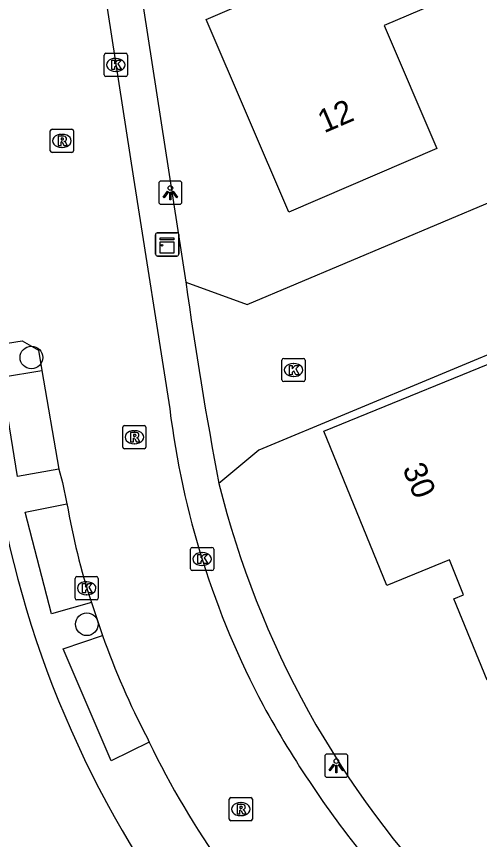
# Model space of a CAD drawing. Extents: x 158474 to 159560, y 388525 to 389605.
# Drawn here: x 158564.62 to 158584.59, y 389003.68 to 389039.16 of the extents above; entities that cross this region are included whole.
import ezdxf

# ---------------------------------------------------------------- set-up
doc = ezdxf.new("R2010")
doc.units = 0
for name, color, linetype in [('IMGEO_Boom', 7, 'Continuous'), ('IMGEO_Kast', 7, 'Continuous'), ('IMGEO_Kolk', 7, 'Continuous'), ('IMGEO_Lichtpunt', 7, 'Continuous'), ('IMGEO_Pand', 7, 'Continuous'), ('IMGEO_Pand_nummerreeks', 7, 'Continuous'), ('IMGEO_Rijbaan_lokaal_open', 7, 'Continuous'), ('IMGEO_Rioolput', 7, 'Continuous'), ('IMGEO_Voetpad_open', 7, 'Continuous')]:
    doc.layers.add(name, color=color, linetype=linetype)

msp = doc.modelspace()

# ---------------------------------------------------------------- linework, layer by layer
at = {"layer": 'IMGEO_Boom'}
for centre in [(158565.26, 389024.458), (158567.65, 389012.957)]:
    msp.add_circle(centre, 0.489, dxfattribs=at)
at = {"layer": 'IMGEO_Kast'}
for p, q in [((158570.614, 389028.908), (158570.614, 389029.749)), ((158570.614, 389029.749), (158570.614, 389028.908)), ((158570.689, 389029.833), (158571.53, 389029.833)), ((158571.53, 389029.833), (158570.689, 389029.833)), ((158571.614, 389029.758), (158571.614, 389028.917)), ((158571.614, 389028.917), (158571.614, 389029.758)), ((158571.539, 389028.833), (158570.698, 389028.833)), ((158570.698, 389028.833), (158571.539, 389028.833))]:
    msp.add_line(p, q, dxfattribs=at)
for points in [[(158570.809, 389029.623), (158571.409, 389029.623), (158571.409, 389029.538), (158570.809, 389029.538), (158570.809, 389029.623)], [(158570.809, 389029.448), (158571.409, 389029.448), (158571.409, 389028.959), (158570.809, 389028.959), (158570.809, 389029.448)]]:
    msp.add_lwpolyline(points, dxfattribs=at)
msp.add_circle((158570.893, 389029.297), 0.0377, dxfattribs=at)
for centre, start, end in [((158570.692, 389029.755), 92.4484, 184.2845), ((158570.692, 389029.755), 92.4484, 184.2845), ((158571.536, 389029.755), 2.4484, 94.2845), ((158571.536, 389029.755), 2.4484, 94.2845), ((158570.692, 389028.911), 182.4484, 274.2845), ((158570.692, 389028.911), 182.4484, 274.2845), ((158571.536, 389028.911), 272.4484, 4.2845), ((158571.536, 389028.911), 272.4484, 4.2845)]:
    msp.add_arc(centre, 0.0779, start, end, dxfattribs=at)
at = {"layer": 'IMGEO_Kolk'}
for p, q in [((158568.401, 389036.646), (158568.401, 389037.498)), ((158568.476, 389037.572), (158569.328, 389037.572)), ((158568.889, 389037.352), (158568.914, 389037.352)), ((158569.402, 389037.498), (158569.402, 389036.646)), ((158568.912, 389036.792), (158568.887, 389036.792)), ((158569.328, 389036.572), (158568.476, 389036.572)), ((158576.066, 389023.492), (158576.066, 389024.344)), ((158576.141, 389024.418), (158576.993, 389024.418)), ((158576.554, 389024.198), (158576.579, 389024.198)), ((158577.067, 389024.344), (158577.067, 389023.492)), ((158576.577, 389023.638), (158576.552, 389023.638)), ((158576.993, 389023.418), (158576.141, 389023.418)), ((158572.121, 389015.345), (158572.121, 389016.197)), ((158572.196, 389016.271), (158573.048, 389016.271)), ((158572.609, 389016.051), (158572.634, 389016.051)), ((158573.122, 389016.197), (158573.122, 389015.345)), ((158572.632, 389015.491), (158572.607, 389015.491)), ((158567.218, 389015.009), (158568.07, 389015.009)), ((158573.048, 389015.271), (158572.196, 389015.271)), ((158567.143, 389014.083), (158567.143, 389014.935)), ((158567.631, 389014.789), (158567.656, 389014.789)), ((158568.144, 389014.935), (158568.144, 389014.083)), ((158568.07, 389014.009), (158567.218, 389014.009)), ((158567.654, 389014.229), (158567.629, 389014.229))]:
    msp.add_line(p, q, dxfattribs=at)
for points in [[(158568.401, 389036.646), (158568.401, 389037.498)], [(158568.476, 389037.572), (158569.328, 389037.572)], [(158569.402, 389037.498), (158569.402, 389036.646)], [(158568.722, 389037.272), (158568.845, 389037.272), (158568.845, 389037.121), (158568.975, 389037.272), (158569.139, 389037.272), (158568.993, 389037.121), (158569.146, 389036.872), (158568.994, 389036.872), (158568.909, 389037.036), (158568.845, 389036.969), (158568.845, 389036.872), (158568.722, 389036.872), (158568.722, 389037.272)], [(158569.328, 389036.572), (158568.476, 389036.572)], [(158576.066, 389023.492), (158576.066, 389024.344)], [(158576.141, 389024.418), (158576.993, 389024.418)], [(158577.067, 389024.344), (158577.067, 389023.492)], [(158576.387, 389024.118), (158576.51, 389024.118), (158576.51, 389023.967), (158576.64, 389024.118), (158576.804, 389024.118), (158576.658, 389023.967), (158576.811, 389023.718), (158576.659, 389023.718), (158576.574, 389023.882), (158576.51, 389023.815), (158576.51, 389023.718), (158576.387, 389023.718), (158576.387, 389024.118)], [(158576.993, 389023.418), (158576.141, 389023.418)], [(158572.121, 389015.345), (158572.121, 389016.197)], [(158572.196, 389016.271), (158573.048, 389016.271)], [(158573.122, 389016.197), (158573.122, 389015.345)], [(158572.442, 389015.971), (158572.565, 389015.971), (158572.565, 389015.82), (158572.695, 389015.971), (158572.859, 389015.971), (158572.713, 389015.82), (158572.866, 389015.571), (158572.714, 389015.571), (158572.629, 389015.735), (158572.565, 389015.668), (158572.565, 389015.571), (158572.442, 389015.571), (158572.442, 389015.971)], [(158567.218, 389015.009), (158568.07, 389015.009)], [(158573.048, 389015.271), (158572.196, 389015.271)], [(158567.143, 389014.083), (158567.143, 389014.935)], [(158567.464, 389014.709), (158567.587, 389014.709), (158567.587, 389014.558), (158567.717, 389014.709), (158567.881, 389014.709), (158567.735, 389014.558), (158567.888, 389014.309), (158567.736, 389014.309), (158567.651, 389014.473), (158567.587, 389014.406), (158567.587, 389014.309), (158567.464, 389014.309), (158567.464, 389014.709)], [(158568.144, 389014.935), (158568.144, 389014.083)], [(158568.07, 389014.009), (158567.218, 389014.009)]]:
    msp.add_lwpolyline(points, dxfattribs=at)
for centre, start, end in [((158568.478, 389037.496), 91.552, 178.448), ((158568.478, 389037.496), 91.552, 178.448), ((158569.326, 389037.496), 1.552, 88.448), ((158569.326, 389037.496), 1.552, 88.448), ((158568.478, 389036.648), 181.552, 268.448), ((158568.478, 389036.648), 181.552, 268.448), ((158569.326, 389036.648), 271.552, 358.448), ((158569.326, 389036.648), 271.552, 358.448), ((158576.143, 389024.342), 91.552, 178.448), ((158576.143, 389024.342), 91.552, 178.448), ((158576.991, 389024.342), 1.552, 88.448), ((158576.991, 389024.342), 1.552, 88.448), ((158576.143, 389023.494), 181.552, 268.448), ((158576.143, 389023.494), 181.552, 268.448), ((158576.991, 389023.494), 271.552, 358.448), ((158576.991, 389023.494), 271.552, 358.448), ((158572.198, 389016.195), 91.552, 178.448), ((158572.198, 389016.195), 91.552, 178.448), ((158573.046, 389016.195), 1.552, 88.448), ((158573.046, 389016.195), 1.552, 88.448), ((158572.198, 389015.347), 181.552, 268.448), ((158572.198, 389015.347), 181.552, 268.448), ((158573.046, 389015.347), 271.552, 358.448), ((158573.046, 389015.347), 271.552, 358.448), ((158567.22, 389014.933), 91.552, 178.448), ((158567.22, 389014.933), 91.552, 178.448), ((158568.068, 389014.933), 1.552, 88.448), ((158568.068, 389014.933), 1.552, 88.448), ((158567.22, 389014.085), 181.552, 268.448), ((158567.22, 389014.085), 181.552, 268.448), ((158568.068, 389014.085), 271.552, 358.448), ((158568.068, 389014.085), 271.552, 358.448)]:
    msp.add_arc(centre, 0.0765, start, end, dxfattribs=at)
for centre, major_axis, ratio, start_param, end_param in [((158568.888, 389037.072), (-0.387, 0.002), 0.722429, 4.712389, 7.853982), ((158568.913, 389037.072), (-0.39, 0.002), 0.717154, 1.570796, 4.712389), ((158576.553, 389023.918), (-0.387, 0.002), 0.722429, 4.712389, 7.853982), ((158576.578, 389023.918), (-0.39, 0.002), 0.717154, 1.570796, 4.712389), ((158572.608, 389015.771), (-0.387, 0.002), 0.722429, 4.712389, 7.853982), ((158572.633, 389015.771), (-0.39, 0.002), 0.717154, 1.570796, 4.712389), ((158567.63, 389014.509), (-0.387, 0.002), 0.722429, 4.712389, 7.853982), ((158567.655, 389014.509), (-0.39, 0.002), 0.717154, 1.570796, 4.712389)]:
    msp.add_ellipse(centre, major_axis=major_axis, ratio=ratio, start_param=start_param, end_param=end_param, dxfattribs=at)
at = {"layer": 'IMGEO_Lichtpunt'}
for p, q in [((158571.657, 389032.062), (158570.849, 389032.062)), ((158571.657, 389032.062), (158570.849, 389032.062)), ((158570.755, 389031.967), (158570.755, 389031.16)), ((158570.755, 389031.967), (158570.755, 389031.16)), ((158571.751, 389031.16), (158571.751, 389031.967)), ((158571.751, 389031.16), (158571.751, 389031.967)), ((158570.849, 389031.066), (158571.657, 389031.066)), ((158570.849, 389031.066), (158571.657, 389031.066)), ((158577.913, 389007.262), (158577.913, 389006.455)), ((158577.913, 389007.262), (158577.913, 389006.455)), ((158578.815, 389007.357), (158578.007, 389007.357)), ((158578.815, 389007.357), (158578.007, 389007.357)), ((158578.909, 389006.455), (158578.909, 389007.262)), ((158578.909, 389006.455), (158578.909, 389007.262)), ((158578.007, 389006.361), (158578.815, 389006.361)), ((158578.007, 389006.361), (158578.815, 389006.361))]:
    msp.add_line(p, q, dxfattribs=at)
for points in [[(158571.129, 389031.631), (158571.168, 389031.603), (158570.98, 389031.341), (158570.942, 389031.368), (158571.129, 389031.631)], [(158571.231, 389031.583), (158571.278, 389031.583), (158571.278, 389031.261), (158571.231, 389031.261), (158571.231, 389031.583)], [(158571.341, 389031.603), (158571.379, 389031.63), (158571.566, 389031.368), (158571.527, 389031.34), (158571.341, 389031.603)], [(158578.287, 389006.926), (158578.326, 389006.898), (158578.138, 389006.636), (158578.1, 389006.663), (158578.287, 389006.926)], [(158578.389, 389006.878), (158578.436, 389006.878), (158578.436, 389006.556), (158578.389, 389006.556), (158578.389, 389006.878)], [(158578.499, 389006.898), (158578.537, 389006.925), (158578.724, 389006.663), (158578.685, 389006.635), (158578.499, 389006.898)]]:
    msp.add_lwpolyline(points, dxfattribs=at)
for centre in [(158571.254, 389031.765), (158578.412, 389007.06)]:
    msp.add_circle(centre, 0.0994, dxfattribs=at)
for centre, start, end in [((158570.849, 389031.967), 90, 180), ((158570.849, 389031.967), 90, 180), ((158571.657, 389031.967), 0, 90), ((158571.657, 389031.967), 0, 90), ((158570.849, 389031.16), 180, 270), ((158570.849, 389031.16), 180, 270), ((158571.657, 389031.16), 270, 0), ((158571.657, 389031.16), 270, 360), ((158578.007, 389007.262), 90, 180), ((158578.007, 389007.262), 90, 180), ((158578.815, 389007.262), 0, 90), ((158578.815, 389007.262), 0, 90), ((158578.007, 389006.455), 180, 270), ((158578.007, 389006.455), 180, 270), ((158578.815, 389006.455), 270, 0), ((158578.815, 389006.455), 270, 360)]:
    msp.add_arc(centre, 0.0946, start, end, dxfattribs=at)
at = {"layer": 'IMGEO_Pand'}
for points in [[(158584.194, 389040.362), (158580.476, 389038.767), (158582.751, 389033.466), (158576.363, 389030.724), (158572.797, 389039.033), (158579.179, 389041.772), (158578.097, 389044.293), (158581.821, 389045.891), (158584.194, 389040.362)], [(158584.911, 389010.545), (158583.477, 389014.054), (158583.901, 389014.227), (158583.286, 389015.732), (158580.588, 389014.629), (158577.869, 389021.279), (158586.822, 389024.939), (158589.582, 389018.188), (158590.376, 389018.512), (158592.384, 389013.6), (158584.911, 389010.545)]]:
    msp.add_lwpolyline(points, dxfattribs=at)
at = {"layer": 'IMGEO_Rijbaan_lokaal_open'}
for points in [[(158564.949, 389062.628), (158569.658, 389032.192), (158571.227, 389022.248)], [(158567.204, 389058.167), (158571.923, 389027.713)], [(158571.923, 389027.713), (158574.563, 389026.742), (158591.467, 389033.868)], [(158593.802, 389028.26), (158586.677, 389025.294), (158575.064, 389020.458), (158573.349, 389019.024)], [(158562.866, 389024.858), (158564.862, 389025.171), (158565.571, 389024.773), (158565.711, 389023.893)], [(158565.711, 389023.893), (158566.45, 389019.648)], [(158566.45, 389019.648), (158566.603, 389019.063), (158566.791, 389018.156)], [(158567.852, 389013.891), (158568.331, 389012.466)], [(158570.247, 389008.074), (158570.339, 389007.879)]]:
    msp.add_lwpolyline(points, dxfattribs=at)
for centre, radius, start, end in [((158735.328, 389050.069), 164.927, 187.79039, 190.8497), ((158607.823, 389026.75), 36.872, 187.0131, 207.95), ((158612.509, 389028.748), 40.35, 193.9452, 224.0034), ((158596.602, 389023.308), 30.253, 189.8044, 198.1353), ((158601.001, 389024.104), 34.681, 199.6078, 207.5304), ((158614.722, 389031.136), 45.027, 208.7652, 219.2339), ((158603.848, 389024.055), 37.209, 205.7679, 215.5063)]:
    msp.add_arc(centre, radius, start, end, dxfattribs=at)
at = {"layer": 'IMGEO_Rioolput'}
for p, q in [((158566.076, 389033.372), (158566.076, 389034.224)), ((158566.151, 389034.298), (158567.003, 389034.298)), ((158567.077, 389034.224), (158567.077, 389033.372)), ((158566.564, 389034.078), (158566.589, 389034.078)), ((158566.587, 389033.518), (158566.562, 389033.518)), ((158567.003, 389033.298), (158566.151, 389033.298)), ((158569.201, 389020.596), (158569.201, 389021.448)), ((158569.276, 389021.522), (158570.128, 389021.522)), ((158570.202, 389021.448), (158570.202, 389020.596)), ((158569.689, 389021.302), (158569.714, 389021.302)), ((158569.712, 389020.742), (158569.687, 389020.742)), ((158570.128, 389020.522), (158569.276, 389020.522)), ((158573.791, 389004.56), (158573.791, 389005.412)), ((158573.866, 389005.486), (158574.718, 389005.486)), ((158574.792, 389005.412), (158574.792, 389004.56)), ((158574.279, 389005.266), (158574.304, 389005.266)), ((158574.302, 389004.706), (158574.277, 389004.706)), ((158574.718, 389004.486), (158573.866, 389004.486))]:
    msp.add_line(p, q, dxfattribs=at)
for points in [[(158566.076, 389033.372), (158566.076, 389034.224)], [(158566.151, 389034.298), (158567.003, 389034.298)], [(158567.077, 389034.224), (158567.077, 389033.372)], [(158566.665, 389033.996), (158566.413, 389033.998), (158566.413, 389033.598)], [(158566.591, 389033.917), (158566.537, 389033.917), (158566.537, 389033.836)], [(158566.537, 389033.836), (158566.589, 389033.836)], [(158566.413, 389033.598), (158566.537, 389033.598), (158566.537, 389033.76), (158566.548, 389033.76)], [(158566.595, 389033.731), (158566.666, 389033.598), (158566.806, 389033.598), (158566.741, 389033.724)], [(158567.003, 389033.298), (158566.151, 389033.298)], [(158569.201, 389020.596), (158569.201, 389021.448)], [(158569.276, 389021.522), (158570.128, 389021.522)], [(158570.202, 389021.448), (158570.202, 389020.596)], [(158569.79, 389021.22), (158569.538, 389021.222), (158569.538, 389020.822)], [(158569.716, 389021.141), (158569.662, 389021.141), (158569.662, 389021.06)], [(158569.662, 389021.06), (158569.714, 389021.06)], [(158569.538, 389020.822), (158569.662, 389020.822), (158569.662, 389020.984), (158569.673, 389020.984)], [(158569.72, 389020.955), (158569.791, 389020.822), (158569.931, 389020.822), (158569.866, 389020.948)], [(158570.128, 389020.522), (158569.276, 389020.522)], [(158573.791, 389004.56), (158573.791, 389005.412)], [(158573.866, 389005.486), (158574.718, 389005.486)], [(158574.792, 389005.412), (158574.792, 389004.56)], [(158574.38, 389005.184), (158574.128, 389005.186), (158574.128, 389004.786)], [(158574.306, 389005.105), (158574.252, 389005.105), (158574.252, 389005.024)], [(158574.252, 389005.024), (158574.304, 389005.024)], [(158574.128, 389004.786), (158574.252, 389004.786), (158574.252, 389004.948), (158574.263, 389004.948)], [(158574.31, 389004.919), (158574.381, 389004.786), (158574.521, 389004.786), (158574.456, 389004.912)], [(158574.718, 389004.486), (158573.866, 389004.486)]]:
    msp.add_lwpolyline(points, dxfattribs=at)
for centre, radius, start, end in [((158566.153, 389034.222), 0.0765, 91.552, 178.448), ((158566.153, 389034.222), 0.0765, 91.552, 178.448), ((158567.001, 389034.222), 0.0765, 1.552, 88.448), ((158567.001, 389034.222), 0.0765, 1.552, 88.448), ((158566.573, 389034.025), 0.19, 274.7715, 282.9687), ((158566.597, 389033.821), 0.0964, 77.0061, 93.1865), ((158566.611, 389033.878), 0.0378, 276.6634, 79.6772), ((158566.664, 389033.886), 0.109, 350.3612, 89.416), ((158566.662, 389033.886), 0.112, 277.5842, 350.9817), ((158566.646, 389033.671), 0.108, 29.5134, 73.7905), ((158566.547, 389033.707), 0.0533, 26.0293, 88.6989), ((158566.153, 389033.374), 0.0765, 181.552, 268.448), ((158566.153, 389033.374), 0.0765, 181.552, 268.448), ((158567.001, 389033.374), 0.0765, 271.552, 358.448), ((158567.001, 389033.374), 0.0765, 271.552, 358.448), ((158569.278, 389021.446), 0.0765, 91.552, 178.448), ((158569.278, 389021.446), 0.0765, 91.552, 178.448), ((158570.126, 389021.446), 0.0765, 1.552, 88.448), ((158570.126, 389021.446), 0.0765, 1.552, 88.448), ((158569.698, 389021.249), 0.19, 274.7715, 282.9687), ((158569.722, 389021.045), 0.0964, 77.0061, 93.1865), ((158569.736, 389021.102), 0.0378, 276.6634, 79.6772), ((158569.789, 389021.11), 0.109, 350.3612, 89.416), ((158569.787, 389021.11), 0.112, 277.5842, 350.9817), ((158569.771, 389020.895), 0.108, 29.5134, 73.7905), ((158569.672, 389020.931), 0.0533, 26.0293, 88.6989), ((158569.278, 389020.598), 0.0765, 181.552, 268.448), ((158569.278, 389020.598), 0.0765, 181.552, 268.448), ((158570.126, 389020.598), 0.0765, 271.552, 358.448), ((158570.126, 389020.598), 0.0765, 271.552, 358.448), ((158573.868, 389005.41), 0.0765, 91.552, 178.448), ((158573.868, 389005.41), 0.0765, 91.552, 178.448), ((158574.716, 389005.41), 0.0765, 1.552, 88.448), ((158574.716, 389005.41), 0.0765, 1.552, 88.448), ((158574.288, 389005.213), 0.19, 274.7715, 282.9687), ((158574.312, 389005.009), 0.0964, 77.0061, 93.1865), ((158574.326, 389005.066), 0.0378, 276.6634, 79.6772), ((158574.379, 389005.074), 0.109, 350.3612, 89.416), ((158574.377, 389005.074), 0.112, 277.5842, 350.9817), ((158574.262, 389004.895), 0.0533, 26.0293, 88.6989), ((158574.361, 389004.859), 0.108, 29.5134, 73.7905), ((158573.868, 389004.562), 0.0765, 181.552, 268.448), ((158573.868, 389004.562), 0.0765, 181.552, 268.448), ((158574.716, 389004.562), 0.0765, 271.552, 358.448), ((158574.716, 389004.562), 0.0765, 271.552, 358.448)]:
    msp.add_arc(centre, radius, start, end, dxfattribs=at)
for centre, major_axis, ratio, start_param, end_param in [((158566.563, 389033.798), (-0.387, 0.002), 0.722429, 4.712389, 7.853982), ((158566.588, 389033.798), (-0.39, 0.002), 0.717154, 1.570796, 4.712389), ((158569.688, 389021.022), (-0.387, 0.002), 0.722429, 4.712389, 7.853982), ((158569.713, 389021.022), (-0.39, 0.002), 0.717154, 1.570796, 4.712389), ((158574.278, 389004.986), (-0.387, 0.002), 0.722429, 4.712389, 7.853982), ((158574.303, 389004.986), (-0.39, 0.002), 0.717154, 1.570796, 4.712389)]:
    msp.add_ellipse(centre, major_axis=major_axis, ratio=ratio, start_param=start_param, end_param=end_param, dxfattribs=at)
at = {"layer": 'IMGEO_Voetpad_open'}
for points in [[(158566.45, 389019.648), (158564.658, 389019.328), (158563.969, 389023.607), (158565.711, 389023.893)], [(158567.852, 389013.891), (158566.131, 389013.401), (158564.993, 389017.787), (158566.791, 389018.156)], [(158570.339, 389007.879), (158568.704, 389007.076), (158566.631, 389011.892), (158568.331, 389012.466)]]:
    msp.add_lwpolyline(points, dxfattribs=at)
msp.add_arc((158607.781, 389026.445), 44.627, 187.8492, 216.3397, dxfattribs=at)

# ---------------------------------------------------------------- texts
at = {"layer": 'IMGEO_Pand_nummerreeks'}
for s, rotation, p in [('12', 23.2311, (158577.884, 389034.12)), ('30', 292.2383, (158581.25, 389019.671))]:
    msp.add_text(s, height=1, rotation=rotation, dxfattribs=at).set_placement(p)

doc.saveas('drawing.dxf')
